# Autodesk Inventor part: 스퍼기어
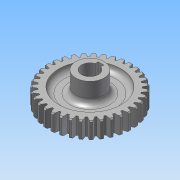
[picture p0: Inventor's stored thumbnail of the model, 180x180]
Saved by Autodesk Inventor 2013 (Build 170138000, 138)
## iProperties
Created: 2013-08
Part Number: 스퍼기어
Material: 강
Document SubType Name: Modeling
Designer: 한국산업디자인학원
Categories: <?xml version="1.0" encoding="UTF-16"?> <MemberInstance><Categories><FamilyTemplate><FamilyTemplateParameter ValueType="xs:double" Id="1" ObjectReferenceKey="da
Density: 1 g/cm^3
CustomPartVersion: 1
Author: 한국산업디자인학원
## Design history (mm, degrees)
sketch "Sketch1"
  geometry: C1 r 37 at (0, 0)
  constraints: 1 centre point
  dimensions: "d0" = 74 diameter of C1 (= da_da)
extrude "Extrusion1" new body sketch "Sketch1" distance "d1" = 15 (= da_b); taper "d2" = 0 deg
chamfer "모따기1" distance "d49" = 1; stored, may be unused: second distance "d50" = 2, angle "d51" = 45 deg
workplane "Work Plane2"
feature "피치 지름" dims "d4" = 10, "d5" = 0
workplane "Work Plane8"
workplane "Work Plane9"
feature "스퍼 기어" dims "da_b" = 15, "da_d" = 70, "da_aw" = 70, "da_da" = 74, "da_df" = 65, "da_dw" = 70, angle "da_beta" = 0 deg, "da_lefttooth" = 0, "da_righttooth" = 0
node "작업 평면11"
sketch "스케치3"
  geometry: L1 (-2.5, 7.071)-(-2.5, 9.8); L2 (-2.5, 9.8)-(2.5, 9.8); L3 (2.5, 9.8)-(2.5, 7.071); C1 r 12.5 at (0, 0); A1 r 7.5 centre (0, 0) between (-2.5, 7.071) and (2.5, 7.071); 1 further point
  constraints: 6 end point, 2 centre point, 2 coincident, 2 parallel, 2 point on circle, 1 perpendicular, 1 vertical
  dimensions: "d53" = 25 diameter of C1; "d55" = 15 diameter of A1; "d56" = 5 distance of L1.end L2.end; "d57" = 17.3 dimension on A1 L2
extrude "돌출2" join sketch "스케치3" distance "d58" = 31; taper "d59" = 0 deg
sketch "스케치4"
  geometry: L1 (2.5, 7.071)-(2.5, 9.8) reference; L2 (2.5, 9.8)-(-2.5, 9.8) reference; L3 (-2.5, 9.8)-(-2.5, 7.071) reference; A1 r 7.5 centre (0, 0) between (-2.5, 7.071) and (2.5, 7.071) reference; A2 r 7.5 centre (0, 0) between (-2.5, 7.071) and (2.5, 7.071) reference
extrude "돌출3" cut sketch "스케치3" stored distance "d60" = 31; taper "d61" = 0 deg
sketch "스케치5"
  geometry: C1 r 12.5 at (0, 0) reference; C2 r 27.5 at (0, 0); C3 r 12.5 at (0, 0) reference
  constraints: 1 centre point, 1 coincident
  dimensions: "d62" = 55 diameter of C2
extrude "돌출4" cut sketch "스케치5" distance "d64" = 5; taper "d65" = 0 deg
sketch "스케치6"
  geometry: C1 r 12.5 at (0, 0) reference; C2 r 27.5 at (0, 0) reference; C3 r 12.5 at (0, 0) reference
extrude "돌출5" cut sketch "스케치6" distance "d66" = 5; taper "d67" = 0 deg
fillet "모깎기1" dims "d68" = 5
body "Solid1"
sketch "Sketch2"
  geometry: C1 r 37 at (0, 0) reference; C2 r 35 at (0, 0)
  constraints: 1 centre point, 1 coincident
  dimensions: "d3" = 70 diameter of C2 (= da_dw)
body "Srf1"
other parameters: "d17" = 0, "d34" = 0.8976 (computed from da_z), "d39" = 0, "d41" = 0, "d47" = 0, "d48" = 0, "d52" = 3
